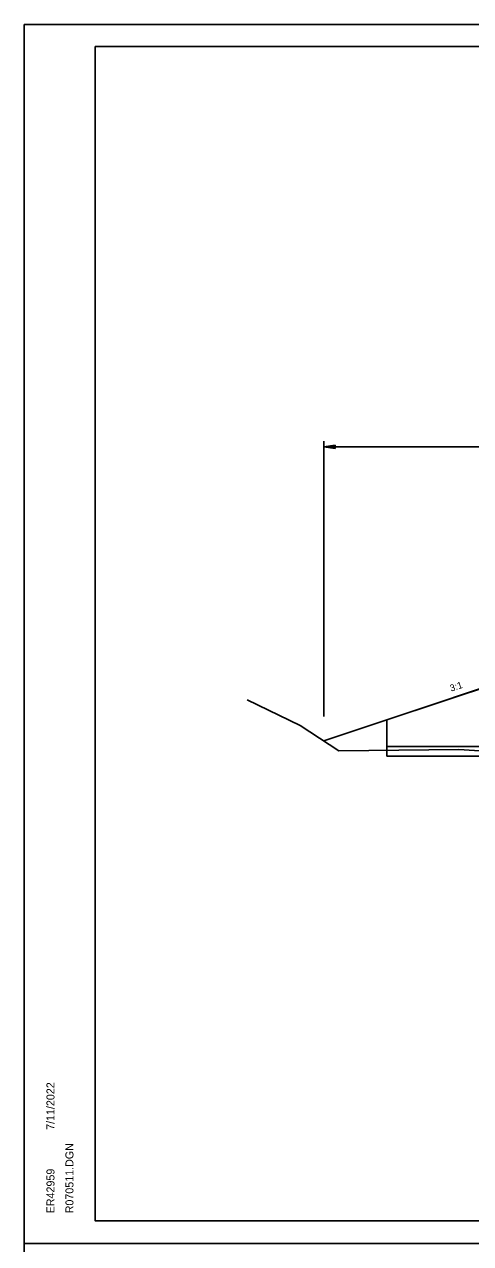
# Model space of a CAD drawing. Extents: x 1398460 to 1408037, y 380768 to 383968.
# Drawn here: x 1400666 to 1401056, y 382901 to 383968 of the extents above; entities that cross this region are included whole.
import ezdxf

# ---------------------------------------------------------------- set-up
doc = ezdxf.new("R2010")
doc.units = 0
for name, color, linetype in [('R_Border', 7, 'Continuous'), ('R_Dimension', 7, 'Continuous'), ('R_Draft', 7, 'Continuous'), ('R_Exist Surface', 7, 'Continuous'), ('R_Fin Surface', 7, 'Continuous'), ('R_No Plot', 7, 'Continuous'), ('R_Water', 7, 'Continuous')]:
    doc.layers.add(name, color=color, linetype=linetype)

msp = doc.modelspace()

# ---------------------------------------------------------------- linework, layer by layer
at = {"layer": 'R_Border'}
for p, q in [((1400727.6, 383948.1), (1402308.5, 383948.1)), ((1400727.6, 382920.8), (1400727.6, 383948.1)), ((1400727.6, 382920.8), (1400727.6, 382920.8)), ((1402308.5, 382920.8), (1400727.6, 382920.8))]:
    msp.add_line(p, q, dxfattribs=at)
at = {"layer": 'R_Dimension'}
for p, q in [((1400927.7, 383362.2), (1400927.7, 383602.9)), ((1400937.7, 383599.4), (1400927.7, 383597.9)), ((1400927.7, 383597.9), (1401498.9, 383597.9)), ((1400937.7, 383596.4), (1400927.7, 383597.9)), ((1400937.7, 383599.2), (1400929.4, 383597.9)), ((1400937.7, 383596.7), (1400929.4, 383597.9)), ((1400937.7, 383598.9), (1400931.1, 383597.9)), ((1400937.7, 383596.9), (1400931.1, 383597.9)), ((1400937.7, 383598.7), (1400932.8, 383597.9)), ((1400937.7, 383597.2), (1400932.8, 383597.9)), ((1400937.7, 383598.4), (1400934.5, 383597.9)), ((1400937.7, 383597.4), (1400934.5, 383597.9)), ((1400937.7, 383598.1), (1400936.2, 383597.9)), ((1400937.7, 383597.7), (1400936.2, 383597.9)), ((1400937.7, 383596.4), (1400937.7, 383599.4))]:
    msp.add_line(p, q, dxfattribs=at)
at = {"layer": 'R_Exist Surface'}
msp.add_lwpolyline([(1400860.6, 383376.7), (1400907, 383354.3), (1400940.9, 383332.1), (1401045.8, 383333.1), (1401151.1, 383326.4), (1401196.7, 383331.1), (1401202.2, 383331.6), (1401276.3, 383380.5), (1401326.9, 383424), (1401338.8, 383437.3), (1401356.2, 383438.6), (1401392.3, 383441.4), (1401426.8, 383442.8), (1401496.1, 383445.5), (1401531.4, 383445.3), (1401595.8, 383444.6), (1401631.2, 383443), (1401649.9, 383442.1), (1401667.5, 383439.4), (1401669.3, 383439), (1401672.6, 383434.4), (1401687, 383422.3), (1401773.4, 383346.7)], dxfattribs=at)
at = {"layer": 'R_Fin Surface'}
msp.add_lwpolyline([(1401164.2, 383416.2), (1401154.2, 383416.2), (1400927.7, 383340.7)], dxfattribs=at)
at = {"layer": 'R_No Plot'}
for p, q in [((1400665.6, 383967.6), (1402332.2, 383967.6)), ((1400665.6, 382900.9), (1402332.2, 382900.9)), ((1400665.6, 382900.9), (1402332.2, 382900.9))]:
    msp.add_line(p, q, dxfattribs=at)
for points in [[(1400665.5, 383967.6), (1402332.2, 383967.6), (1402332.2, 382900.9), (1400665.5, 382900.9)], [(1401897.2, 383948.1), (1401995.3, 383948.1), (1401995.3, 383898.7), (1402075.8, 383898.7), (1402191.8, 383898.7), (1402191.8, 383777), (1402308.5, 383777), (1402308.5, 382920.8), (1400727.6, 382920.8), (1400727.6, 383948.1)], [(1400665.5, 382900.9), (1402332.2, 382900.9), (1402332.2, 381834.2), (1400665.5, 381834.2)]]:
    msp.add_lwpolyline(points, close=True, dxfattribs=at)
at = {"layer": 'R_Water'}
for p, q in [((1400982.8, 383359.1), (1401154.2, 383416.2)), ((1400982.8, 383335.8), (1400982.8, 383359.1)), ((1400982.8, 383335.8), (1400982.8, 383327.4)), ((1401154.2, 383335.8), (1400982.8, 383335.8)), ((1401154.2, 383327.4), (1400982.8, 383327.4))]:
    msp.add_line(p, q, dxfattribs=at)

# ---------------------------------------------------------------- texts
at = {"layer": 'R_Border'}
for s, p in [('7/11/2022', (1400691.9, 383000.4)), ('R070511.DGN', (1400708.5, 382927.4)), ('ER42959', (1400691.9, 382927.4))]:
    msp.add_text(s, height=7, rotation=90, dxfattribs=at).set_placement(p)
at = {"layer": 'R_Draft'}
msp.add_text('3:1', height=6, rotation=18.4348, dxfattribs=at).set_placement((1401039.2, 383383.7))

doc.saveas('drawing.dxf')
